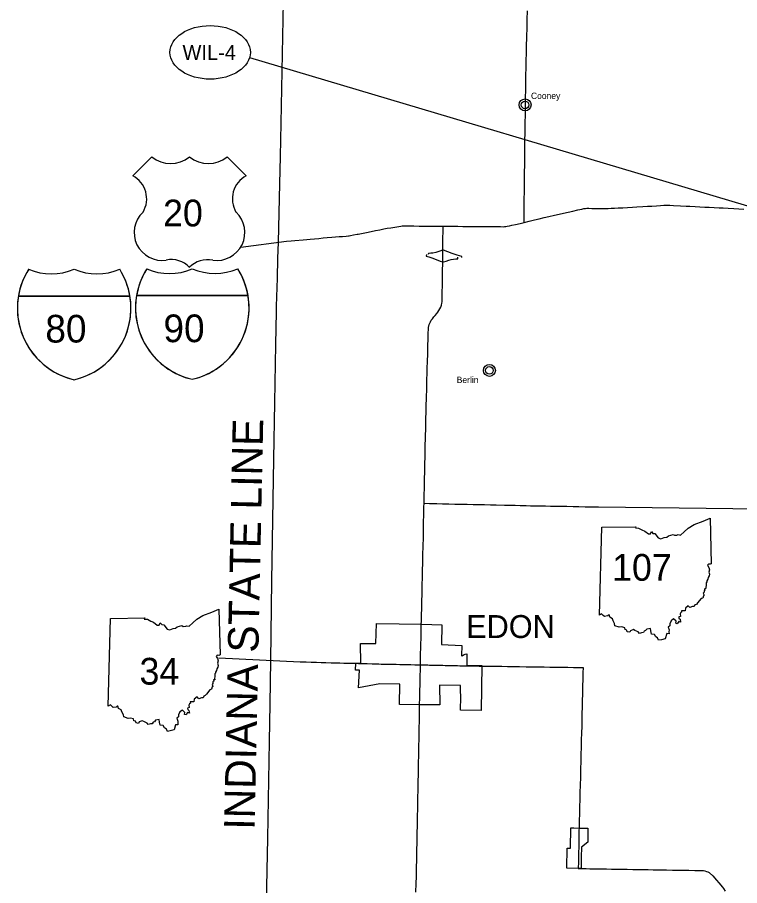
# Model space of a CAD drawing. Extents: x -66 to 795, y 0 to 440.
# Drawn here: x 115.9 to 250.6, y 175.4 to 337.3 of the extents above; entities that cross this region are included whole.
import ezdxf

# ---------------------------------------------------------------- set-up
doc = ezdxf.new("R2010")
doc.units = 0
for name, color, linetype in [('DV_X_Corp_Line', 7, 'Continuous'), ('GM_X_Adjacent_County_Text', 7, 'Continuous'), ('GM_X_Corporation_Text', 7, 'Continuous'), ('GM_X_County', 7, 'Continuous'), ('GM_X_Interchange_Ramps', 7, 'Continuous'), ('GM_X_State_Route', 7, 'Continuous'), ('GM_X_US_Route', 7, 'Continuous'), ('PV_P_Text', 7, 'Continuous'), ('SH_Data', 7, 'Continuous')]:
    doc.layers.add(name, color=color, linetype=linetype)

msp = doc.modelspace()

# ---------------------------------------------------------------- linework, layer by layer
at = {"layer": 'DV_X_Corp_Line'}
for points in [[(179, 216.9), (179.92, 216.89), (179.91, 220.56), (182.77, 220.56), (182.86, 224.29), (191.32, 224.18), (195.06, 224.05), (195, 220.36), (198.79, 220.19), (198.7, 218.29), (198.83, 218.19), (199.02, 218.37), (199.2, 218.5), (199.4, 218.54), (199.72, 218.63), (199.72, 218.46), (199.71, 216.5), (202.5, 216.44), (202.4, 208.08), (198.53, 208.09), (198.57, 210.63), (198.54, 211.77), (198.53, 212.74), (194.62, 212.78), (194.66, 209.11), (190.99, 209.12), (187.16, 209.17), (187.22, 212.95), (183.46, 213.02), (179.51, 212.25), (179.71, 215.57), (178.97, 215.56)], [(219.14, 186.15), (219.66, 186.14), (220.64, 186.13), (222.27, 186.1), (222.28, 184.78), (222.27, 183.49), (221.08, 182.54), (221.08, 182.38), (221.08, 182), (221.06, 181.23), (221.04, 180.03), (221.04, 178.59), (220.47, 178.6), (218.37, 178.62), (218.42, 182.37), (219.06, 182.36)]]:
    msp.add_lwpolyline(points, close=True, dxfattribs=at)
for centre, radius in [((210.58, 320.99), 1.12), ((210.58, 320.99), 0.71), ((203.93, 271.48), 1.12), ((203.93, 271.48), 0.71)]:
    msp.add_circle(centre, radius, dxfattribs=at)
at = {"layer": 'GM_X_County'}
msp.add_lwpolyline([(165.44, 340.23), (165.03, 317.58), (164.89, 311.34), (164.76, 306.25), (164.5, 295.37), (164.43, 292.33), (164.34, 288.68), (164.18, 283.46), (164.15, 282.41), (164.05, 276.31), (163.85, 265.5), (163.63, 254.95), (163.54, 247.37), (163.29, 232.26), (163.07, 217.4), (163, 209.31), (162.85, 202.28), (162.51, 184.25), (162.31, 172.16)], dxfattribs=at)
at = {"layer": 'GM_X_Interchange_Ramps'}
for points in [[(192.18, 293.09), (192.16, 292.77), (192.65, 292.63), (193.35, 292.39), (194.73, 291.86), (195.18, 291.7), (195.22, 291.7)], [(195.25, 293.89), (195.18, 293.89), (194.67, 293.7), (193.93, 293.48), (193.38, 293.36), (192.99, 293.31), (192.55, 293.3), (192.53, 293.06)], [(198.79, 292.5), (198.81, 292.72), (198.32, 292.82), (197.89, 292.94), (197.01, 293.26), (195.36, 293.89), (195.25, 293.89)], [(195.22, 291.7), (195.36, 291.7), (195.84, 291.84), (196.36, 292.03), (196.81, 292.14), (197.25, 292.23), (197.68, 292.28), (198.03, 292.29), (198.06, 292.58)]]:
    msp.add_lwpolyline(points, dxfattribs=at)
at = {"layer": 'GM_X_State_Route'}
msp.add_line((224.27, 246.03), (308.22, 244.92), dxfattribs=at)
for points in [[(210.39, 299.07), (210.4, 300.34), (210.42, 301.75), (210.44, 303.33), (210.46, 304.81), (210.46, 305.71), (210.46, 305.83), (210.47, 307.11), (210.49, 308.38), (210.51, 309.81), (210.53, 311.31), (210.55, 312.98), (210.55, 313.34), (210.56, 314.44), (210.59, 315.73), (210.62, 317.5), (210.64, 319.26), (210.66, 320.89), (210.68, 322.39), (210.7, 323.71), (210.73, 325.18), (210.75, 326.55), (210.77, 327.92), (210.78, 328.35), (210.8, 329.24), (210.83, 330.62), (210.87, 331.94), (210.91, 333.61), (210.94, 335.47), (210.96, 335.98), (210.98, 336.94), (211.03, 338.54)], [(195.26, 294.97), (195.26, 295.39), (195.27, 295.98), (195.3, 297.58), (195.32, 298.37)], [(195.23, 292.83), (195.25, 293.89), (195.26, 294.96), (195.26, 294.97)], [(195.19, 289.22), (195.19, 289.26), (195.19, 289.31), (195.2, 290.28), (195.21, 291.21), (195.22, 291.7), (195.23, 292.83)], [(195.12, 284.56), (195.12, 284.57), (195.13, 284.6), (195.13, 285.08), (195.14, 286.1), (195.16, 287.25), (195.17, 287.86), (195.18, 288.54), (195.19, 289.22)], [(192.54, 278.9), (192.54, 278.91), (192.56, 279.39), (192.57, 279.5), (192.7, 280.03), (192.8, 280.31), (192.92, 280.55), (193.09, 280.84), (193.29, 281.11), (193.58, 281.45), (193.81, 281.71), (194.1, 282.07), (194.32, 282.35), (194.51, 282.62), (194.7, 282.96), (194.85, 283.28), (194.97, 283.64), (195.06, 284), (195.1, 284.29), (195.12, 284.56)], [(191.73, 246.7), (191.77, 248.09), (191.8, 249.7), (191.84, 251.15), (191.84, 251.41), (191.86, 252.36), (191.89, 253.87), (191.92, 255.56), (191.97, 257.24), (192, 259), (192.05, 260.81), (192.09, 262.48), (192.11, 263.66), (192.13, 264.38), (192.13, 264.75), (192.18, 266.43), (192.23, 268.02), (192.27, 269.57), (192.32, 271.1), (192.34, 271.89), (192.38, 273.14), (192.42, 274.57), (192.46, 276.06), (192.5, 277.35), (192.53, 278.66), (192.54, 278.9)], [(191.3, 226.96), (191.3, 227.02), (191.32, 228.3), (191.36, 229.88), (191.38, 231.24), (191.39, 231.63), (191.42, 232.72), (191.45, 234.14), (191.49, 235.57), (191.53, 237.1), (191.56, 238.68), (191.61, 240.31), (191.63, 241.82), (191.66, 243.17), (191.69, 244.54), (191.71, 245.94), (191.73, 246.7)], [(191.73, 246.7), (192.77, 246.66), (194.13, 246.64), (195.2, 246.62), (196.35, 246.59), (197.47, 246.56), (198.62, 246.54), (199.78, 246.51), (200.88, 246.48), (202.02, 246.45), (203.01, 246.44), (204.12, 246.41), (205.16, 246.39), (206.77, 246.36), (207, 246.36), (207.81, 246.34), (208.76, 246.32), (209.69, 246.3), (210.8, 246.28), (211.62, 246.25), (212.53, 246.24), (213.46, 246.22), (214.37, 246.2), (215.32, 246.18), (216.34, 246.17), (217.4, 246.16), (218.37, 246.13), (219.52, 246.1), (220.61, 246.08), (221.8, 246.06), (222.08, 246.06), (222.78, 246.05), (223.79, 246.04), (224.27, 246.03)], [(191.23, 224.1), (191.23, 224.1), (191.24, 224.76), (191.27, 225.99), (191.3, 226.96)], [(191.17, 221.23), (191.19, 222.11), (191.22, 223.42), (191.23, 224.1)], [(191.15, 220.18), (191.15, 220.76), (191.17, 221.23)], [(191.09, 217.92), (191.09, 217.92), (191.1, 218.52), (191.1, 218.61), (191.14, 219.74), (191.14, 219.83), (191.15, 220.18), (191.15, 220.18)], [(153.46, 217.85), (168.65, 217.14), (169.75, 217.11), (170.68, 217.08), (171.69, 217.05), (172.54, 217.03), (173.42, 217), (174.39, 216.97), (175.28, 216.94), (176.01, 216.93), (176.8, 216.9), (177.92, 216.87), (178.9, 216.85), (178.9, 216.85)], [(191.08, 216.57), (191.08, 217.41), (191.09, 217.47)], [(191.09, 217.47), (191.09, 217.47), (191.09, 217.49), (191.09, 217.92)], [(178.9, 216.85), (179.02, 216.85), (179.51, 216.83)], [(179.51, 216.83), (180.1, 216.81), (180.88, 216.79)], [(180.88, 216.79), (181.12, 216.79), (182.05, 216.77), (183.16, 216.73), (183.32, 216.73)], [(183.32, 216.73), (183.32, 216.73), (183.77, 216.72)], [(183.77, 216.72), (183.78, 216.72), (184.08, 216.71), (184.99, 216.7)], [(184.99, 216.7), (184.99, 216.7), (185.05, 216.69), (185.65, 216.68), (186.43, 216.67), (186.47, 216.67), (186.51, 216.67)], [(186.51, 216.67), (186.52, 216.67), (187.24, 216.64), (187.34, 216.64), (187.97, 216.63), (188.34, 216.62), (188.64, 216.61), (189.25, 216.6)], [(189.25, 216.6), (189.27, 216.6), (189.28, 216.6), (190.01, 216.58)], [(190.01, 216.58), (190.02, 216.58), (190.1, 216.58), (190.18, 216.58), (190.47, 216.58)], [(190.47, 216.58), (190.47, 216.58), (191.08, 216.57), (191.94, 216.55), (192.28, 216.54)], [(191.02, 214.28), (191.02, 214.29), (191.02, 214.61), (191.05, 215.51), (191.05, 215.62), (191.08, 216.57)], [(192.28, 216.54), (192.28, 216.54), (192.44, 216.54), (192.74, 216.53), (193.33, 216.52), (193.5, 216.52), (193.9, 216.51), (194.29, 216.5), (195.22, 216.48), (195.69, 216.47), (195.98, 216.47), (197.07, 216.44), (197.99, 216.42), (198.42, 216.41)], [(198.42, 216.41), (198.46, 216.41), (198.62, 216.41), (198.82, 216.4), (199.47, 216.39)], [(199.47, 216.39), (199.71, 216.39), (200.48, 216.38), (201.2, 216.37), (202, 216.35), (202.17, 216.35)], [(202.17, 216.35), (202.21, 216.35), (202.65, 216.35), (203.52, 216.33), (204.17, 216.33), (205.13, 216.31), (205.17, 216.31)], [(205.17, 216.31), (206.22, 216.31), (207.3, 216.28), (208.49, 216.27), (209.53, 216.25), (210.78, 216.22), (212.15, 216.21), (213.25, 216.19), (214.16, 216.17), (215.19, 216.16), (216.31, 216.15), (217.29, 216.13), (218.54, 216.11), (219.6, 216.09), (220.56, 216.07), (221.39, 216.06), (221.38, 215.1), (221.35, 213.9), (221.32, 212.56), (221.28, 211.2), (221.25, 209.77), (221.22, 208.67), (221.19, 207.49), (221.17, 206.41), (221.14, 205.16), (221.11, 203.8), (221.07, 202.57), (221.04, 201.13), (221.01, 199.91), (220.98, 198.59), (220.93, 197.1), (220.9, 195.59), (220.86, 194.11), (220.82, 192.79), (220.78, 191.47), (220.75, 190.09), (220.71, 188.79), (220.68, 187.51), (220.65, 186.39), (220.65, 186.34), (220.65, 186.34)], [(190.99, 212.61), (191.01, 213.52), (191.01, 213.54), (191.02, 214.28)], [(190.94, 210.18), (190.95, 210.72), (190.98, 212.03), (190.99, 212.61)], [(190.23, 174.2), (190.28, 175.79), (190.3, 177.1), (190.34, 178.7), (190.37, 180.29), (190.41, 181.94), (190.44, 183.52), (190.48, 185.19), (190.51, 186.58), (190.54, 188.02), (190.57, 190.04), (190.6, 191.76), (190.63, 193.27), (190.64, 194.66), (190.68, 196.25), (190.71, 198.18), (190.75, 199.8), (190.77, 201.22), (190.78, 201.5), (190.8, 202.63), (190.84, 204.59), (190.87, 206.31), (190.9, 208.08), (190.91, 208.96), (190.91, 208.96)], [(190.91, 208.96), (190.92, 209.4), (190.94, 210.18)], [(220.65, 186.34), (220.64, 186.03), (220.63, 185.82), (220.62, 184.91), (220.62, 184.8), (220.61, 184.08), (220.59, 183.69), (220.58, 183.38), (220.58, 182.49), (220.55, 181.61), (220.55, 181.21), (220.55, 180.81), (220.52, 179.88), (220.52, 179.83), (220.51, 178.58)], [(220.51, 178.58), (220.95, 178.58)], [(220.95, 178.58), (220.95, 178.58), (221.49, 178.57), (221.99, 178.56)], [(221.99, 178.56), (222.68, 178.55), (223.83, 178.54), (224.8, 178.52), (225.76, 178.51), (226.7, 178.49), (227.74, 178.47), (228.85, 178.45), (229.65, 178.44), (230.66, 178.42), (231.54, 178.41), (232.56, 178.39), (233.51, 178.38), (234.46, 178.36), (235.69, 178.35), (236.95, 178.32), (238.06, 178.3), (239.11, 178.29), (240.1, 178.27), (240.97, 178.25), (241.15, 178.25)], [(241.15, 178.25), (241.15, 178.25), (242.23, 178.23), (243.11, 178.22), (243.64, 178.2), (243.83, 178.19), (244.12, 178.14), (244.41, 178.05), (244.69, 177.95), (244.9, 177.85), (245, 177.78), (245.58, 177.24), (246.28, 176.44), (246.72, 175.94), (247.38, 175.13), (247.56, 174.87), (247.87, 174.36), (247.88, 174.35)]]:
    msp.add_lwpolyline(points, dxfattribs=at)
at = {"layer": 'GM_X_US_Route'}
for points in [[(210.39, 299.07), (211.34, 299.3), (212.34, 299.54), (213.21, 299.74), (214.12, 299.96), (215.02, 300.17), (216.04, 300.4), (216.94, 300.61), (217.75, 300.8), (218.62, 300.99), (219.51, 301.19), (220.45, 301.4), (221.16, 301.56), (221.55, 301.64), (221.86, 301.69), (222.11, 301.7), (222.48, 301.7), (223.06, 301.69), (223.87, 301.67), (224.81, 301.66), (225.45, 301.65), (225.72, 301.65), (226.08, 301.67), (226.64, 301.7), (227.26, 301.73), (227.93, 301.78), (228.83, 301.82), (229.7, 301.87), (230.61, 301.92), (231.44, 301.96), (232.56, 302.02), (233.43, 302.08), (234.23, 302.12), (235.09, 302.17), (235.87, 302.21), (236.49, 302.26), (236.91, 302.26), (237.21, 302.27), (237.58, 302.26), (238.27, 302.23), (239.54, 302.17), (240.61, 302.13), (241.32, 302.08), (242.32, 302.03), (243.17, 301.99), (244.08, 301.94), (244.91, 301.9), (245.86, 301.85), (246.77, 301.81), (247.53, 301.77), (248.43, 301.72), (249.52, 301.67), (250.45, 301.62), (251.38, 301.57)], [(157.57, 294.48), (166.08, 295.57), (166.97, 295.66), (167.63, 295.72), (169.17, 295.82), (169.87, 295.89), (170.52, 295.95), (171.31, 296.03), (172.09, 296.1), (172.92, 296.18), (173.66, 296.24), (174.55, 296.31), (175.22, 296.36), (175.88, 296.42), (176.55, 296.47), (177.19, 296.52), (177.66, 296.58), (177.76, 296.59), (178.05, 296.63), (178.6, 296.74), (179.29, 296.88), (179.42, 296.9), (180.05, 297.03), (181, 297.22), (181.86, 297.38), (182.69, 297.55), (183.49, 297.71), (184.25, 297.85), (184.87, 297.97), (185.56, 298.08), (186.26, 298.2), (187.04, 298.31), (187.38, 298.37), (187.65, 298.41), (187.8, 298.43), (188.08, 298.43), (188.99, 298.42), (189.84, 298.41), (190.81, 298.4), (191.53, 298.39), (192.1, 298.38), (192.96, 298.38), (193.76, 298.38), (194.6, 298.37), (195.32, 298.37)], [(195.32, 298.37), (195.98, 298.37), (196.99, 298.36), (198.01, 298.35), (198.96, 298.34), (199.81, 298.34), (200.86, 298.33), (201.72, 298.32), (202.68, 298.31), (203.54, 298.31), (204.37, 298.3), (205.21, 298.29), (206, 298.29), (206.51, 298.28), (206.76, 298.29), (206.99, 298.31), (207.24, 298.35), (207.69, 298.43), (208.11, 298.53), (208.8, 298.69), (209.66, 298.89), (210.39, 299.07)]]:
    msp.add_lwpolyline(points, dxfattribs=at)
at = {"layer": 'PV_P_Text'}
for p, q in [((140.95, 311.29), (137.4, 307.75)), ((140.95, 311.29), (137.4, 307.75)), ((158.59, 307.75), (155.04, 311.29)), ((158.59, 307.75), (155.04, 311.29)), ((116.08, 285.35), (136.88, 285.35)), ((136.88, 285.35), (116.08, 285.35)), ((136.88, 285.35), (116.08, 285.35)), ((138.11, 285.42), (158.91, 285.42)), ((158.91, 285.42), (138.11, 285.42)), ((158.91, 285.42), (138.11, 285.42)), ((224.44, 225.83), (224.89, 242.21)), ((132.81, 208.83), (133.27, 225.2)), ((132.81, 208.83), (133.27, 225.2))]:
    msp.add_line(p, q, dxfattribs=at)
for points in [[(224.89, 242.21), (231.25, 242.31), (231.15, 242.11), (231.75, 242.07), (232.38, 241.72), (232.92, 241.5), (233.58, 240.98), (233.98, 240.99), (234.14, 241.41), (234.44, 241.08), (234.8, 241.03), (235.42, 240.24), (235.93, 240.07), (236.54, 240.34), (237, 240.38), (237.34, 240.65), (238.21, 240.88), (238.45, 240.74), (238.91, 240.77), (239.15, 240.87), (239.55, 240.78), (240.26, 241.37), (240.99, 242.08), (242.11, 242.74), (243.78, 243.37), (245.11, 243.93), (245.3, 235.43)], [(245.3, 235.43), (245.11, 235.31), (244.8, 235.37), (244.6, 235.13), (244.85, 234.73), (244.97, 234.31), (244.86, 233.85), (244.97, 233.47), (244.9, 233.15), (244.7, 232.83), (244.64, 232.53), (244.48, 232.21), (244.49, 232.03), (244.33, 231.89), (244.36, 231.35), (244.28, 231.06), (244.31, 230.81), (244.06, 230.74), (244.12, 230.53), (243.96, 230.37), (243.99, 230.09), (243.81, 229.91), (243.99, 229.55), (243.84, 229.44), (243.73, 229.01), (243.4, 228.92), (242.76, 228.13), (242.53, 227.83), (242.27, 227.75), (242.13, 227.44), (241.82, 227.44), (241.34, 227.23), (241.03, 227.6), (240.49, 227.15), (240.43, 226.64), (239.75, 226.66), (239.77, 226.4), (239.62, 226.33), (239.48, 226.07), (239.56, 225.61), (239.24, 225.49), (239.28, 225.23), (239.49, 225.06), (239.58, 224.55), (239.24, 224.66), (238.96, 224.23), (238.67, 224.33), (238.77, 224.69), (238.28, 225.13), (237.82, 224.78), (237.59, 224.22), (237.58, 223.84), (237.24, 223.61), (237.46, 223.08), (237.42, 222.71), (237.43, 222.37), (237, 222.38), (236.74, 221.44)], [(133.27, 225.2), (139.63, 225.31), (139.53, 225.11), (140.13, 225.07), (140.76, 224.72), (141.3, 224.5), (141.96, 223.98), (142.35, 223.98), (142.52, 224.41), (142.82, 224.08), (143.18, 224.02), (143.8, 223.24), (144.31, 223.07), (144.92, 223.34), (145.38, 223.38), (145.72, 223.65), (146.59, 223.88), (146.83, 223.74), (147.29, 223.77), (147.52, 223.87), (147.93, 223.78), (148.64, 224.37), (149.36, 225.07), (150.49, 225.74), (152.16, 226.36), (153.49, 226.93), (153.68, 218.43)], [(133.27, 225.2), (139.63, 225.31), (139.53, 225.11), (140.13, 225.07), (140.76, 224.72), (141.3, 224.5), (141.96, 223.98), (142.35, 223.98), (142.52, 224.41), (142.82, 224.08), (143.18, 224.02), (143.8, 223.24), (144.31, 223.07), (144.92, 223.34), (145.38, 223.38), (145.72, 223.65), (146.59, 223.88), (146.83, 223.74), (147.29, 223.77), (147.52, 223.87), (147.93, 223.78), (148.64, 224.37), (149.36, 225.07), (150.49, 225.74), (152.16, 226.36), (153.49, 226.93), (153.68, 218.43)], [(236.74, 221.44), (236, 221.26), (235.49, 221.15), (235.3, 221.58), (234.94, 221.8), (234.7, 222.23), (234.17, 222.29), (234.04, 222.88), (233.98, 223.36), (233.26, 223.24), (233.06, 222.95), (232.81, 222.87), (232.66, 222.58), (232.31, 222.55), (231.93, 222.41), (231.69, 222.7), (231.07, 222.99), (230.8, 223.14), (230.22, 222.91), (230.1, 222.63), (229.64, 222.75), (229.53, 223.06), (229.25, 223.15), (229.19, 223.48), (228.6, 223.65), (228.14, 223.59), (227.34, 223.85), (227.29, 224.28), (227.02, 224.8), (226.88, 225.16), (226.37, 225.44), (226.27, 225.87), (226.1, 225.86), (225.96, 225.68), (225.39, 225.6), (225.17, 225.78), (224.85, 226.08), (224.44, 225.83)], [(153.68, 218.43), (153.48, 218.31), (153.18, 218.37), (152.97, 218.13), (153.23, 217.73), (153.35, 217.31), (153.24, 216.85), (153.35, 216.46), (153.27, 216.14), (153.08, 215.83), (153.02, 215.52), (152.86, 215.2), (152.87, 215.03), (152.71, 214.88), (152.74, 214.35), (152.66, 214.06), (152.69, 213.8), (152.44, 213.74), (152.5, 213.53), (152.34, 213.37), (152.37, 213.09), (152.19, 212.91), (152.37, 212.55), (152.22, 212.44), (152.11, 212.01), (151.78, 211.92), (151.14, 211.12), (150.91, 210.82), (150.65, 210.75), (150.51, 210.44), (150.2, 210.44), (149.72, 210.23), (149.41, 210.59), (148.87, 210.15), (148.81, 209.64), (148.12, 209.66), (148.15, 209.4), (148, 209.32), (147.86, 209.07), (147.94, 208.61), (147.62, 208.49), (147.66, 208.22), (147.86, 208.06), (147.96, 207.55), (147.62, 207.65), (147.34, 207.22), (147.05, 207.32), (147.14, 207.69), (146.66, 208.13), (146.2, 207.78), (145.96, 207.22), (145.96, 206.84), (145.62, 206.61), (145.84, 206.08), (145.8, 205.71), (145.81, 205.36), (145.38, 205.38), (145.12, 204.44)], [(153.68, 218.43), (153.48, 218.31), (153.18, 218.37), (152.97, 218.13), (153.23, 217.73), (153.35, 217.31), (153.24, 216.85), (153.35, 216.46), (153.27, 216.14), (153.08, 215.83), (153.02, 215.52), (152.86, 215.2), (152.87, 215.03), (152.71, 214.88), (152.74, 214.35), (152.66, 214.06), (152.69, 213.8), (152.44, 213.74), (152.5, 213.53), (152.34, 213.37), (152.37, 213.09), (152.19, 212.91), (152.37, 212.55), (152.22, 212.44), (152.11, 212.01), (151.78, 211.92), (151.14, 211.12), (150.91, 210.82), (150.65, 210.75), (150.51, 210.44), (150.2, 210.44), (149.72, 210.23), (149.41, 210.59), (148.87, 210.15), (148.81, 209.64), (148.12, 209.66), (148.15, 209.4), (148, 209.32), (147.86, 209.07), (147.94, 208.61), (147.62, 208.49), (147.66, 208.22), (147.86, 208.06), (147.96, 207.55), (147.62, 207.65), (147.34, 207.22), (147.05, 207.32), (147.14, 207.69), (146.66, 208.13), (146.2, 207.78), (145.96, 207.22), (145.96, 206.84), (145.62, 206.61), (145.84, 206.08), (145.8, 205.71), (145.81, 205.36), (145.38, 205.38), (145.12, 204.44)], [(145.12, 204.44), (144.38, 204.26), (143.86, 204.15), (143.68, 204.58), (143.32, 204.8), (143.08, 205.23), (142.55, 205.29), (142.42, 205.88), (142.36, 206.36), (141.64, 206.24), (141.44, 205.95), (141.19, 205.87), (141.04, 205.57), (140.69, 205.55), (140.31, 205.41), (140.07, 205.7), (139.45, 205.99), (139.18, 206.14), (138.6, 205.91), (138.48, 205.63), (138.02, 205.75), (137.91, 206.06), (137.63, 206.15), (137.57, 206.48), (136.98, 206.65), (136.52, 206.58), (135.72, 206.85), (135.67, 207.27), (135.4, 207.8), (135.25, 208.16), (134.75, 208.44), (134.64, 208.87), (134.48, 208.86), (134.33, 208.68), (133.77, 208.6), (133.55, 208.78), (133.23, 209.08), (132.81, 208.83)], [(145.12, 204.44), (144.38, 204.26), (143.86, 204.15), (143.68, 204.58), (143.32, 204.8), (143.08, 205.23), (142.55, 205.29), (142.42, 205.88), (142.36, 206.36), (141.64, 206.24), (141.44, 205.95), (141.19, 205.87), (141.04, 205.57), (140.69, 205.55), (140.31, 205.41), (140.07, 205.7), (139.45, 205.99), (139.18, 206.14), (138.6, 205.91), (138.48, 205.63), (138.02, 205.75), (137.91, 206.06), (137.63, 206.15), (137.57, 206.48), (136.98, 206.65), (136.52, 206.58), (135.72, 206.85), (135.67, 207.27), (135.4, 207.8), (135.25, 208.16), (134.75, 208.44), (134.64, 208.87), (134.48, 208.86), (134.33, 208.68), (133.77, 208.6), (133.55, 208.78), (133.23, 209.08), (132.81, 208.83)]]:
    msp.add_lwpolyline(points, dxfattribs=at)
for centre, radius, start, end in [((144.47, 315.77), 5.7, 231.813, 308.187), ((144.47, 315.77), 5.7, 231.813, 308.187), ((151.52, 315.77), 5.7, 231.813, 308.187), ((151.52, 315.77), 5.7, 231.813, 308.187), ((135.19, 303.47), 4.82, 329.1175, 62.6108), ((135.19, 303.47), 4.82, 329.1175, 62.6108), ((160.8, 303.47), 4.82, 117.3892, 210.8825), ((160.8, 303.47), 4.82, 117.3892, 210.8825), ((142.87, 297.19), 5.2, 133.0046, 278.7282), ((142.87, 297.19), 5.2, 133.0046, 278.7282), ((153.12, 297.19), 5.2, 261.2718, 46.9954), ((153.12, 297.19), 5.2, 261.2718, 46.9954), ((144.61, 287.5), 4.65, 43.4177, 101.8742), ((144.61, 287.5), 4.65, 43.4177, 101.8742), ((151.47, 287.19), 4.94, 79.9613, 134.7468), ((151.47, 287.19), 4.94, 79.9613, 134.7468), ((129.55, 283.06), 13.67, 147.8216, 256.9941), ((128.7, 283.3), 12.79, 146.654, 170.759), ((122.23, 300.39), 10.91, 247.0848, 292.9105), ((122.23, 300.39), 10.91, 247.0848, 292.9105), ((123.4, 283.06), 13.67, 283.0065, 32.1787), ((130.72, 300.39), 10.91, 247.0916, 292.9084), ((130.72, 300.39), 10.91, 247.0916, 292.9084), ((123.4, 283.06), 13.67, 9.6475, 32.179), ((151.59, 283.13), 13.67, 147.8216, 256.9941), ((150.73, 283.37), 12.79, 146.654, 170.759), ((144.26, 300.45), 10.91, 247.0848, 292.9105), ((144.26, 300.45), 10.91, 247.0848, 292.9105), ((145.43, 283.13), 13.67, 283.0065, 32.1787), ((152.76, 300.46), 10.91, 247.0916, 292.9084), ((152.76, 300.46), 10.91, 247.0916, 292.9084), ((145.43, 283.13), 13.67, 9.6475, 32.179), ((129.55, 283.06), 13.67, 170.3514, 256.9967), ((123.43, 283.05), 13.64, 282.7667, 9.6898), ((151.58, 283.13), 13.67, 170.3514, 256.9967), ((145.46, 283.12), 13.64, 282.7667, 9.6898)]:
    msp.add_arc(centre, radius, start, end, dxfattribs=at)
at = {"layer": 'SH_Data'}
msp.add_line((159.19, 329.81), (315.62, 283.27), dxfattribs=at)
msp.add_ellipse((151.84, 330.79), major_axis=(7.5, 0), ratio=0.666667, dxfattribs=at)

# ---------------------------------------------------------------- texts
at = {"layer": 'DV_X_Corp_Line'}
for s, p in [('Cooney', (211.68, 322.09)), ('Berlin', (197.83, 269.12))]:
    msp.add_text(s, height=1.188, rotation=0, dxfattribs=at).set_placement(p)
at = {"layer": 'GM_X_Adjacent_County_Text'}
msp.add_text('INDIANA STATE LINE', height=5.7, rotation=88.7861, dxfattribs=at).set_placement((160.13, 185.77))
at = {"layer": 'GM_X_Corporation_Text'}
msp.add_text('EDON', height=4.275, rotation=0, dxfattribs=at).set_placement((199.6, 221.57))
at = {"layer": 'PV_P_Text'}
for s, height, p in [('20', 4.987, (143.06, 298.33)), ('80', 5.162, (121.1, 276.67)), ('90', 5.162, (143.13, 276.74)), ('107', 4.987, (226.81, 232.25)), ('34', 4.987, (138.67, 212.88))]:
    msp.add_text(s, height=height, dxfattribs=at).set_placement(p)
at = {"layer": 'SH_Data'}
msp.add_text('WIL-4', height=2.8, dxfattribs=at).set_placement((146.68, 329.39))

doc.saveas('drawing.dxf')
